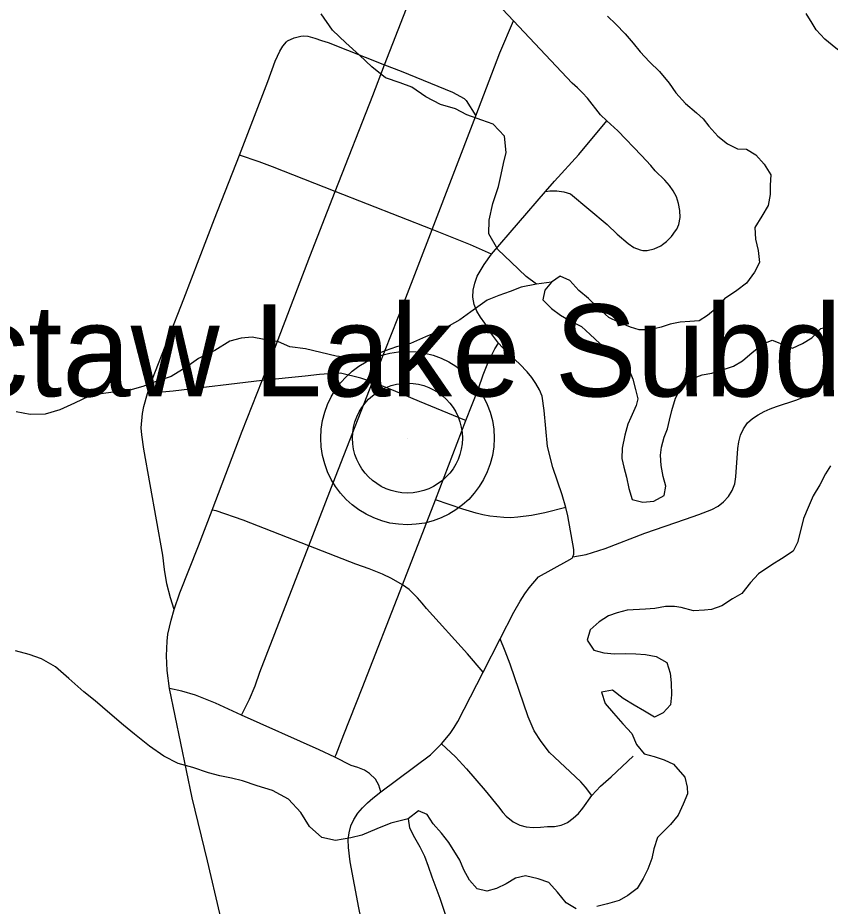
# Model space of a CAD drawing. Extents: x 0 to 36.5, y 0 to 25.3.
# Drawn here: x 4.5 to 5.198, y 19.059 to 19.822 of the extents above; entities that cross this region are included whole.
import ezdxf

# ---------------------------------------------------------------- set-up
doc = ezdxf.new("R2010")
doc.units = 0
for name, color, linetype in [('GM_X_Major_Lake', 7, 'Continuous'), ('GM_X_Minor_River', 7, 'Continuous'), ('GM_X_Township_Road', 7, 'Continuous'), ('GM_X_Unincorporated', 7, 'Continuous'), ('GM_X_Unincorporated_Location', 7, 'Continuous'), ('GM_X_Unincorporated_Text', 7, 'Continuous')]:
    doc.layers.add(name, color=color, linetype=linetype)

msp = doc.modelspace()

# ---------------------------------------------------------------- linework, layer by layer
at = {"layer": 'GM_X_Major_Lake'}
for points in [[(5.00651, 19.82352), (5.01371, 19.81666), (5.02166, 19.80828), (5.02847, 19.80029), (5.03453, 19.79267), (5.04248, 19.78429), (5.05119, 19.77591), (5.05952, 19.76601), (5.0652, 19.75764), (5.07353, 19.7485), (5.083, 19.7405), (5.08868, 19.73516), (5.0936, 19.72907), (5.10117, 19.72032), (5.10951, 19.71383), (5.11824, 19.70963), (5.12583, 19.70923), (5.13379, 19.70427), (5.14099, 19.69628), (5.14666, 19.68714), (5.14625, 19.6784), (5.14623, 19.67043), (5.14431, 19.66093), (5.13896, 19.65183)], [(5.30119, 19.66469), (5.2955, 19.66965), (5.28831, 19.67917), (5.28188, 19.68754), (5.27507, 19.69706), (5.27016, 19.70581), (5.26638, 19.71266), (5.26147, 19.72141), (5.25731, 19.7294), (5.25239, 19.73777), (5.24824, 19.74652), (5.24106, 19.75679), (5.23614, 19.76516), (5.22971, 19.77392), (5.22062, 19.78306), (5.21114, 19.78954), (5.20243, 19.79603), (5.19295, 19.80365), (5.18575, 19.81165), (5.18235, 19.81735), (5.17706, 19.82572)], [(5.13896, 19.65183), (5.13286, 19.64197), (5.13359, 19.63209), (5.13584, 19.62221), (5.13695, 19.61195), (5.13275, 19.6036), (5.12588, 19.59412), (5.11751, 19.58806), (5.10685, 19.58087), (5.10075, 19.57329), (5.09238, 19.56648), (5.08515, 19.56194), (5.07717, 19.5612), (5.06881, 19.56084), (5.06045, 19.55896), (5.05247, 19.55632), (5.04297, 19.55407), (5.03385, 19.5541), (5.02626, 19.55639), (5.01602, 19.5606), (5.00767, 19.5648), (4.9982, 19.57319), (4.99025, 19.58118), (4.98191, 19.58804), (4.97434, 19.59642), (4.96599, 19.60024), (4.95838, 19.59495), (4.95266, 19.58812), (4.95112, 19.57977), (4.95832, 19.57253), (4.96628, 19.56681), (4.97462, 19.56185), (4.9841, 19.55689), (4.99168, 19.55003), (5.00001, 19.54241), (5.00759, 19.53669), (5.01669, 19.52945), (5.02464, 19.52107), (5.02841, 19.51194), (5.03066, 19.50282), (5.03254, 19.49483), (5.03101, 19.48914), (5.02642, 19.47889), (5.02412, 19.4732), (5.02144, 19.46371), (5.01913, 19.4527), (5.01872, 19.44358), (5.0206, 19.43636), (5.02285, 19.42761), (5.02472, 19.41811), (5.02774, 19.4086), (5.03685, 19.4063), (5.04634, 19.40703), (5.05509, 19.41195), (5.05664, 19.41992), (5.05438, 19.42829), (5.05251, 19.43779), (5.05215, 19.44653), (5.05293, 19.45337), (5.05524, 19.4621), (5.05792, 19.46931), (5.05984, 19.47652), (5.06176, 19.48488), (5.06483, 19.49551), (5.06979, 19.50461), (5.07855, 19.51218), (5.08768, 19.51558), (5.09604, 19.51708), (5.10516, 19.51971), (5.11466, 19.52311), (5.12228, 19.52764), (5.13065, 19.53484), (5.14017, 19.54203), (5.14777, 19.54543), (5.16523, 19.53855), (5.17397, 19.54232), (5.18197, 19.54724), (5.18958, 19.5552), (5.19871, 19.55745)], [(5.19798, 19.4374), (5.19379, 19.43057), (5.18882, 19.42109), (5.1831, 19.41161), (5.17889, 19.40174)], [(5.17889, 19.40174), (5.17468, 19.39225), (5.17238, 19.38276), (5.16969, 19.37175), (5.16587, 19.36416), (5.15597, 19.35773), (5.1476, 19.35243), (5.13619, 19.34487), (5.12933, 19.33729), (5.1217, 19.32781), (5.11372, 19.32327), (5.10458, 19.31722), (5.09584, 19.3142), (5.08976, 19.31346), (5.08026, 19.3131), (5.06963, 19.31579), (5.06394, 19.31657), (5.05634, 19.31659), (5.04722, 19.31509), (5.03924, 19.31435), (5.02329, 19.31363), (5.01493, 19.31138), (5.00732, 19.30874), (4.99933, 19.30344), (4.99171, 19.29662), (4.98903, 19.28789), (4.9947, 19.27914), (5.00343, 19.27684), (5.01254, 19.27605), (5.02166, 19.27641), (5.03078, 19.276), (5.03913, 19.2756), (5.04824, 19.27368), (5.05734, 19.26871), (5.06036, 19.25959), (5.06109, 19.25122), (5.06144, 19.24097), (5.06066, 19.23223), (5.05418, 19.22541), (5.04695, 19.22163), (5.03823, 19.22697), (5.02951, 19.23193), (5.02003, 19.23766), (5.01094, 19.2449), (5.00143, 19.24303), (5.00445, 19.23352), (5.01164, 19.22514), (5.01959, 19.216), (5.02754, 19.20762), (5.03131, 19.19811), (5.03813, 19.19012), (5.04648, 19.18782), (5.0552, 19.18513), (5.06317, 19.18131), (5.07301, 19.17027), (5.07489, 19.16152), (5.07525, 19.15582), (5.07143, 19.14709), (5.06722, 19.13761), (5.06074, 19.12965), (5.04931, 19.11828), (5.04625, 19.10879), (5.04471, 19.10043), (5.04126, 19.09132), (5.03706, 19.08336), (5.0321, 19.07463), (5.0241, 19.06857), (5.01649, 19.06441), (5.00661, 19.0614), (4.99749, 19.05914)], [(4.97963, 19.05729), (4.97091, 19.06226), (4.96372, 19.07139), (4.95614, 19.07977), (4.94704, 19.08284), (4.93603, 19.08553), (4.92767, 19.08365), (4.91968, 19.07873), (4.91131, 19.07457), (4.90295, 19.07232), (4.8946, 19.07424), (4.88816, 19.08186), (4.88325, 19.09061), (4.87985, 19.09898), (4.8704, 19.1142), (4.86397, 19.12219), (4.85678, 19.13019), (4.85186, 19.13818), (4.84427, 19.14124), (4.83552, 19.13443), (4.83663, 19.12683), (4.84079, 19.11846), (4.84532, 19.11046), (4.84948, 19.10247), (4.85249, 19.09373), (4.85588, 19.0846), (4.86267, 19.06635), (4.86493, 19.0595), (4.86756, 19.05189)]]:
    msp.add_lwpolyline(points, dxfattribs=at)
at = {"layer": 'GM_X_Minor_River'}
for points in [[(4.94546, 19.59346), (4.93675, 19.59994), (4.92386, 19.61213), (4.9125, 19.62318), (4.90456, 19.6365), (4.90498, 19.64828), (4.90806, 19.6627), (4.91304, 19.67713), (4.91534, 19.68738), (4.91727, 19.69687), (4.91957, 19.70636), (4.9181, 19.72042), (4.90825, 19.73071), (4.89876, 19.73415), (4.88586, 19.73874), (4.876, 19.74371), (4.8631, 19.74754), (4.85058, 19.75403), (4.83845, 19.76242), (4.82858, 19.76625), (4.81606, 19.77046), (4.80432, 19.77999), (4.79371, 19.78989), (4.78196, 19.80056), (4.7706, 19.81123), (4.76076, 19.82531)], [(4.95838, 19.59495), (4.94546, 19.59346), (4.93254, 19.59084), (4.92303, 19.58706), (4.91315, 19.58367), (4.90326, 19.57952), (4.88918, 19.56968), (4.87966, 19.56286), (4.86406, 19.55379), (4.85038, 19.54813), (4.83744, 19.54246), (4.82528, 19.53945), (4.81578, 19.53606), (4.80589, 19.53229), (4.79335, 19.52966), (4.78385, 19.53045), (4.7736, 19.53161), (4.76032, 19.53469), (4.74741, 19.53776), (4.73374, 19.5397), (4.72426, 19.5439), (4.71173, 19.54583), (4.70148, 19.54776), (4.69198, 19.54703), (4.68248, 19.54439), (4.66954, 19.53645), (4.65547, 19.52965), (4.64557, 19.52245), (4.63188, 19.51413), (4.61743, 19.50923), (4.60754, 19.50546), (4.59652, 19.50245), (4.58208, 19.50059), (4.57182, 19.4991), (4.56156, 19.49722), (4.54901, 19.49118), (4.53646, 19.48551), (4.52391, 19.48175), (4.511, 19.4814), (4.49885, 19.48371)], [(4.83552, 19.13443), (4.82069, 19.13067), (4.80852, 19.12576), (4.79559, 19.12048), (4.78609, 19.11822), (4.77317, 19.11598), (4.7614, 19.11829), (4.75079, 19.12782), (4.74323, 19.14), (4.73263, 19.15142), (4.71898, 19.15868), (4.7057, 19.16289), (4.69317, 19.1671), (4.68368, 19.16941), (4.67382, 19.17133), (4.66395, 19.17402), (4.65067, 19.17861), (4.63814, 19.18207), (4.62562, 19.18818), (4.6135, 19.19695), (4.60061, 19.20724), (4.59114, 19.21487), (4.57939, 19.22478), (4.56689, 19.23583), (4.55704, 19.24345), (4.54415, 19.25488), (4.53279, 19.26479), (4.52065, 19.27166), (4.51003, 19.27549), (4.49826, 19.27856)]]:
    msp.add_lwpolyline(points, dxfattribs=at)
at = {"layer": 'GM_X_Township_Road'}
for p, q in [((4.92571, 19.81945), (4.85076, 19.89922)), ((4.85601, 19.64037), (4.89352, 19.73785)), ((4.85601, 19.64037), (4.7728, 19.67294)), ((4.90689, 19.61914), (4.95341, 19.67287)), ((4.85876, 19.40831), (4.88492, 19.47642)), ((4.83043, 19.33534), (4.85876, 19.40831)), ((4.89967, 19.26025), (4.9144, 19.28888))]:
    msp.add_line(p, q, dxfattribs=at)
for points in [[(4.81513, 19.7817), (4.83869, 19.84193), (4.84359, 19.85332), (4.84768, 19.86499), (4.85003, 19.87072), (4.85185, 19.87663), (4.85296, 19.88269), (4.85313, 19.88888), (4.85214, 19.89502), (4.85076, 19.89922)], [(4.89352, 19.73785), (4.91421, 19.79181), (4.92571, 19.81945)], [(5.00604, 19.73359), (5.00057, 19.7386), (4.9894, 19.7529), (4.98521, 19.75748), (4.98085, 19.76187), (4.97619, 19.76598), (4.92571, 19.81945)], [(4.69058, 19.70395), (4.71504, 19.76718), (4.72131, 19.78484), (4.72527, 19.79337), (4.72789, 19.79759), (4.73085, 19.80129), (4.7319, 19.80212), (4.73748, 19.80481), (4.7433, 19.80633), (4.74586, 19.80646), (4.74939, 19.80619), (4.75526, 19.80459), (4.76094, 19.80237), (4.76684, 19.80084), (4.81513, 19.7817)], [(4.7728, 19.67294), (4.80521, 19.75542), (4.81513, 19.7817)], [(4.81513, 19.7817), (4.82938, 19.77614), (4.87349, 19.75806), (4.88336, 19.75284), (4.88535, 19.75112), (4.89352, 19.73785)], [(4.95341, 19.67287), (4.95708, 19.67339), (4.96307, 19.67349), (4.96915, 19.67269), (4.97479, 19.67101), (5.00635, 19.64466), (5.01487, 19.63623), (5.02415, 19.62815), (5.02903, 19.6247), (5.03457, 19.62271), (5.03672, 19.62237), (5.04063, 19.62232), (5.04664, 19.62358), (5.05223, 19.62626), (5.05375, 19.62728), (5.05713, 19.62998), (5.06144, 19.63427), (5.06504, 19.63901), (5.06596, 19.64067), (5.06762, 19.64462), (5.0688, 19.6505), (5.06854, 19.65658), (5.06735, 19.66263), (5.0657, 19.66819), (5.06302, 19.67337), (5.05966, 19.67818), (5.05583, 19.68261), (5.0474, 19.69077), (5.04373, 19.69533), (5.03575, 19.70392), (5.01537, 19.72501), (5.00604, 19.73359)], [(4.95341, 19.67287), (4.96096, 19.68173), (4.98182, 19.70467), (5.00604, 19.73359)], [(4.61163, 19.49961), (4.61584, 19.512), (4.64288, 19.58067), (4.6693, 19.64948), (4.69058, 19.70395)], [(4.7728, 19.67294), (4.71906, 19.69395), (4.70758, 19.69824), (4.69058, 19.70395)], [(4.71023, 19.51063), (4.71558, 19.52399), (4.75102, 19.61714), (4.7728, 19.67294)], [(4.80479, 19.50922), (4.83206, 19.5778), (4.85601, 19.64037)], [(4.90689, 19.61914), (4.88883, 19.62708), (4.85601, 19.64037)], [(4.913, 19.54283), (4.90782, 19.54944), (4.90426, 19.55454), (4.90126, 19.55997), (4.89757, 19.56493), (4.89437, 19.57024), (4.89198, 19.57597), (4.89098, 19.58208), (4.89122, 19.58827), (4.89259, 19.59431), (4.8947, 19.60014), (4.90055, 19.61032), (4.90689, 19.61914)], [(4.88492, 19.47642), (4.89591, 19.50388), (4.89981, 19.5155), (4.90426, 19.52692), (4.90981, 19.53785), (4.913, 19.54283)], [(4.97074, 19.40176), (4.96759, 19.41249), (4.95968, 19.43598), (4.95495, 19.45395), (4.95207, 19.48478), (4.95057, 19.49709), (4.94816, 19.50279), (4.94511, 19.5082), (4.94153, 19.51328), (4.93762, 19.51804), (4.93132, 19.52468), (4.91975, 19.53524), (4.913, 19.54283)], [(4.80479, 19.50922), (4.79475, 19.51258), (4.77726, 19.51685), (4.77127, 19.5168), (4.7594, 19.51592), (4.74714, 19.51429), (4.71023, 19.51063)], [(4.71023, 19.51063), (4.63364, 19.50156), (4.61163, 19.49961)], [(4.66717, 19.39933), (4.69292, 19.46706), (4.71023, 19.51063)], [(4.75026, 19.36871), (4.77297, 19.42793), (4.80479, 19.50922)], [(4.88492, 19.47642), (4.88398, 19.47657), (4.84505, 19.49265), (4.82292, 19.50204), (4.80479, 19.50922)], [(4.63457, 19.31423), (4.6313, 19.32423), (4.62841, 19.33624), (4.62637, 19.34845), (4.62474, 19.36063), (4.61953, 19.3911), (4.60853, 19.45182), (4.6068, 19.46398), (4.60623, 19.47014), (4.60751, 19.48238), (4.60867, 19.48846), (4.61163, 19.49961)], [(4.97668, 19.35945), (4.98824, 19.36137), (5.0046, 19.36636), (5.0385, 19.37965), (5.07339, 19.39153), (5.08485, 19.39572), (5.0961, 19.40001), (5.1014, 19.40295), (5.10623, 19.40666), (5.11033, 19.41115), (5.11355, 19.41633), (5.11575, 19.42201), (5.11677, 19.42804), (5.11833, 19.45217), (5.11918, 19.45796), (5.12072, 19.46374), (5.1232, 19.46932), (5.1268, 19.47437), (5.13111, 19.47816), (5.13594, 19.48133), (5.14108, 19.48396), (5.14629, 19.48644), (5.15171, 19.48849), (5.16818, 19.4939), (5.17609, 19.49691), (5.1841, 19.50094), (5.18902, 19.50426)], [(4.97074, 19.40176), (4.95282, 19.39719), (4.94129, 19.39481), (4.92953, 19.39325), (4.92356, 19.39291), (4.91755, 19.39316), (4.90559, 19.39428), (4.89965, 19.39529), (4.8938, 19.39674), (4.88222, 19.40019), (4.85876, 19.40831)], [(4.97668, 19.35945), (4.97761, 19.36162), (4.97749, 19.36555), (4.97238, 19.39442), (4.97074, 19.40176)], [(4.63457, 19.31423), (4.63952, 19.32841), (4.65545, 19.3687), (4.66717, 19.39933)], [(4.75026, 19.36871), (4.69376, 19.39075), (4.67067, 19.39874), (4.66717, 19.39933)], [(4.69226, 19.22352), (4.69915, 19.2372), (4.70396, 19.24864), (4.70824, 19.26028), (4.75026, 19.36871)], [(4.83043, 19.33534), (4.82117, 19.34077), (4.81331, 19.34442), (4.80194, 19.34888), (4.79044, 19.35297), (4.75026, 19.36871)], [(4.9144, 19.28888), (4.92609, 19.31174), (4.93147, 19.32116), (4.93568, 19.32763), (4.93937, 19.33258), (4.94728, 19.34209), (4.97176, 19.35558), (4.97619, 19.3583), (4.97668, 19.35945)], [(4.77242, 19.18728), (4.77358, 19.18959), (4.78007, 19.20681), (4.79603, 19.24666), (4.83043, 19.33534)], [(4.89967, 19.26025), (4.88639, 19.27611), (4.85107, 19.31488), (4.84742, 19.31967), (4.8434, 19.3242), (4.83622, 19.33119), (4.83043, 19.33534)], [(4.63069, 19.24636), (4.62853, 19.26189), (4.62801, 19.27424), (4.62844, 19.28698), (4.62903, 19.2928), (4.63187, 19.30488), (4.63457, 19.31423)], [(4.99316, 19.15457), (4.98762, 19.16165), (4.98353, 19.1662), (4.97917, 19.17055), (4.96096, 19.18731), (4.95684, 19.19151), (4.9496, 19.20092), (4.94371, 19.21), (4.93854, 19.22196), (4.92299, 19.26713), (4.91878, 19.27831), (4.9144, 19.28888)], [(4.86404, 19.19869), (4.87147, 19.20765), (4.87505, 19.2127), (4.87818, 19.21804), (4.89967, 19.26025)], [(4.69226, 19.22352), (4.67001, 19.23367), (4.65872, 19.23838), (4.65296, 19.24052), (4.64122, 19.24413), (4.63069, 19.24636)], [(4.68429, 19.00807), (4.6631, 19.09832), (4.64998, 19.15249), (4.63069, 19.24636)], [(4.77242, 19.18728), (4.75909, 19.19363), (4.69226, 19.22352)], [(4.81205, 19.15755), (4.85469, 19.18946), (4.86404, 19.19869)], [(4.86404, 19.19869), (4.87593, 19.1877), (4.88561, 19.17735), (4.9014, 19.15886), (4.91298, 19.14478), (4.91665, 19.13987), (4.91946, 19.13678), (4.9256, 19.13193), (4.93127, 19.12906), (4.93677, 19.12746), (4.94281, 19.127), (4.94892, 19.12718), (4.95507, 19.12786), (4.96094, 19.12778), (4.96677, 19.12902), (4.96961, 19.13003), (4.9723, 19.13132), (4.97716, 19.13491), (4.98154, 19.13907), (4.98545, 19.14369), (4.99316, 19.15457)], [(4.81205, 19.15755), (4.8103, 19.16334), (4.80727, 19.16856), (4.80237, 19.17334), (4.79782, 19.17609), (4.79226, 19.17843), (4.78648, 19.1803), (4.77242, 19.18728)], [(4.99316, 19.15457), (5.00062, 19.16238), (5.00973, 19.17051), (5.02853, 19.18833)], [(4.79754, 19.03594), (4.79302, 19.05811), (4.78568, 19.09761), (4.78407, 19.10992), (4.78402, 19.11663), (4.78471, 19.12229), (4.78623, 19.1283), (4.78876, 19.13396), (4.79212, 19.13916), (4.79617, 19.14386), (4.80053, 19.14824), (4.80521, 19.15228), (4.81205, 19.15755)]]:
    msp.add_lwpolyline(points, dxfattribs=at)
at = {"layer": 'GM_X_Unincorporated'}
for radius in [0.0744, 0.04716]:
    msp.add_circle((4.83481, 19.46124), radius, dxfattribs=at)
at = {"layer": 'GM_X_Unincorporated_Location'}
msp.add_line((4.83481, 19.46124), (4.83481, 19.46124), dxfattribs=at)

# ---------------------------------------------------------------- texts
at = {"layer": 'GM_X_Unincorporated_Text'}
msp.add_text('Choctaw Lake Subdivision', height=0.0789773, rotation=0.00001, dxfattribs=at).set_placement((4.26263, 19.49701))

doc.saveas('drawing.dxf')
